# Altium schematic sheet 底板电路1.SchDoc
size 1099 x 400 mm; SheetNumber: 2; SheetTotal: 2
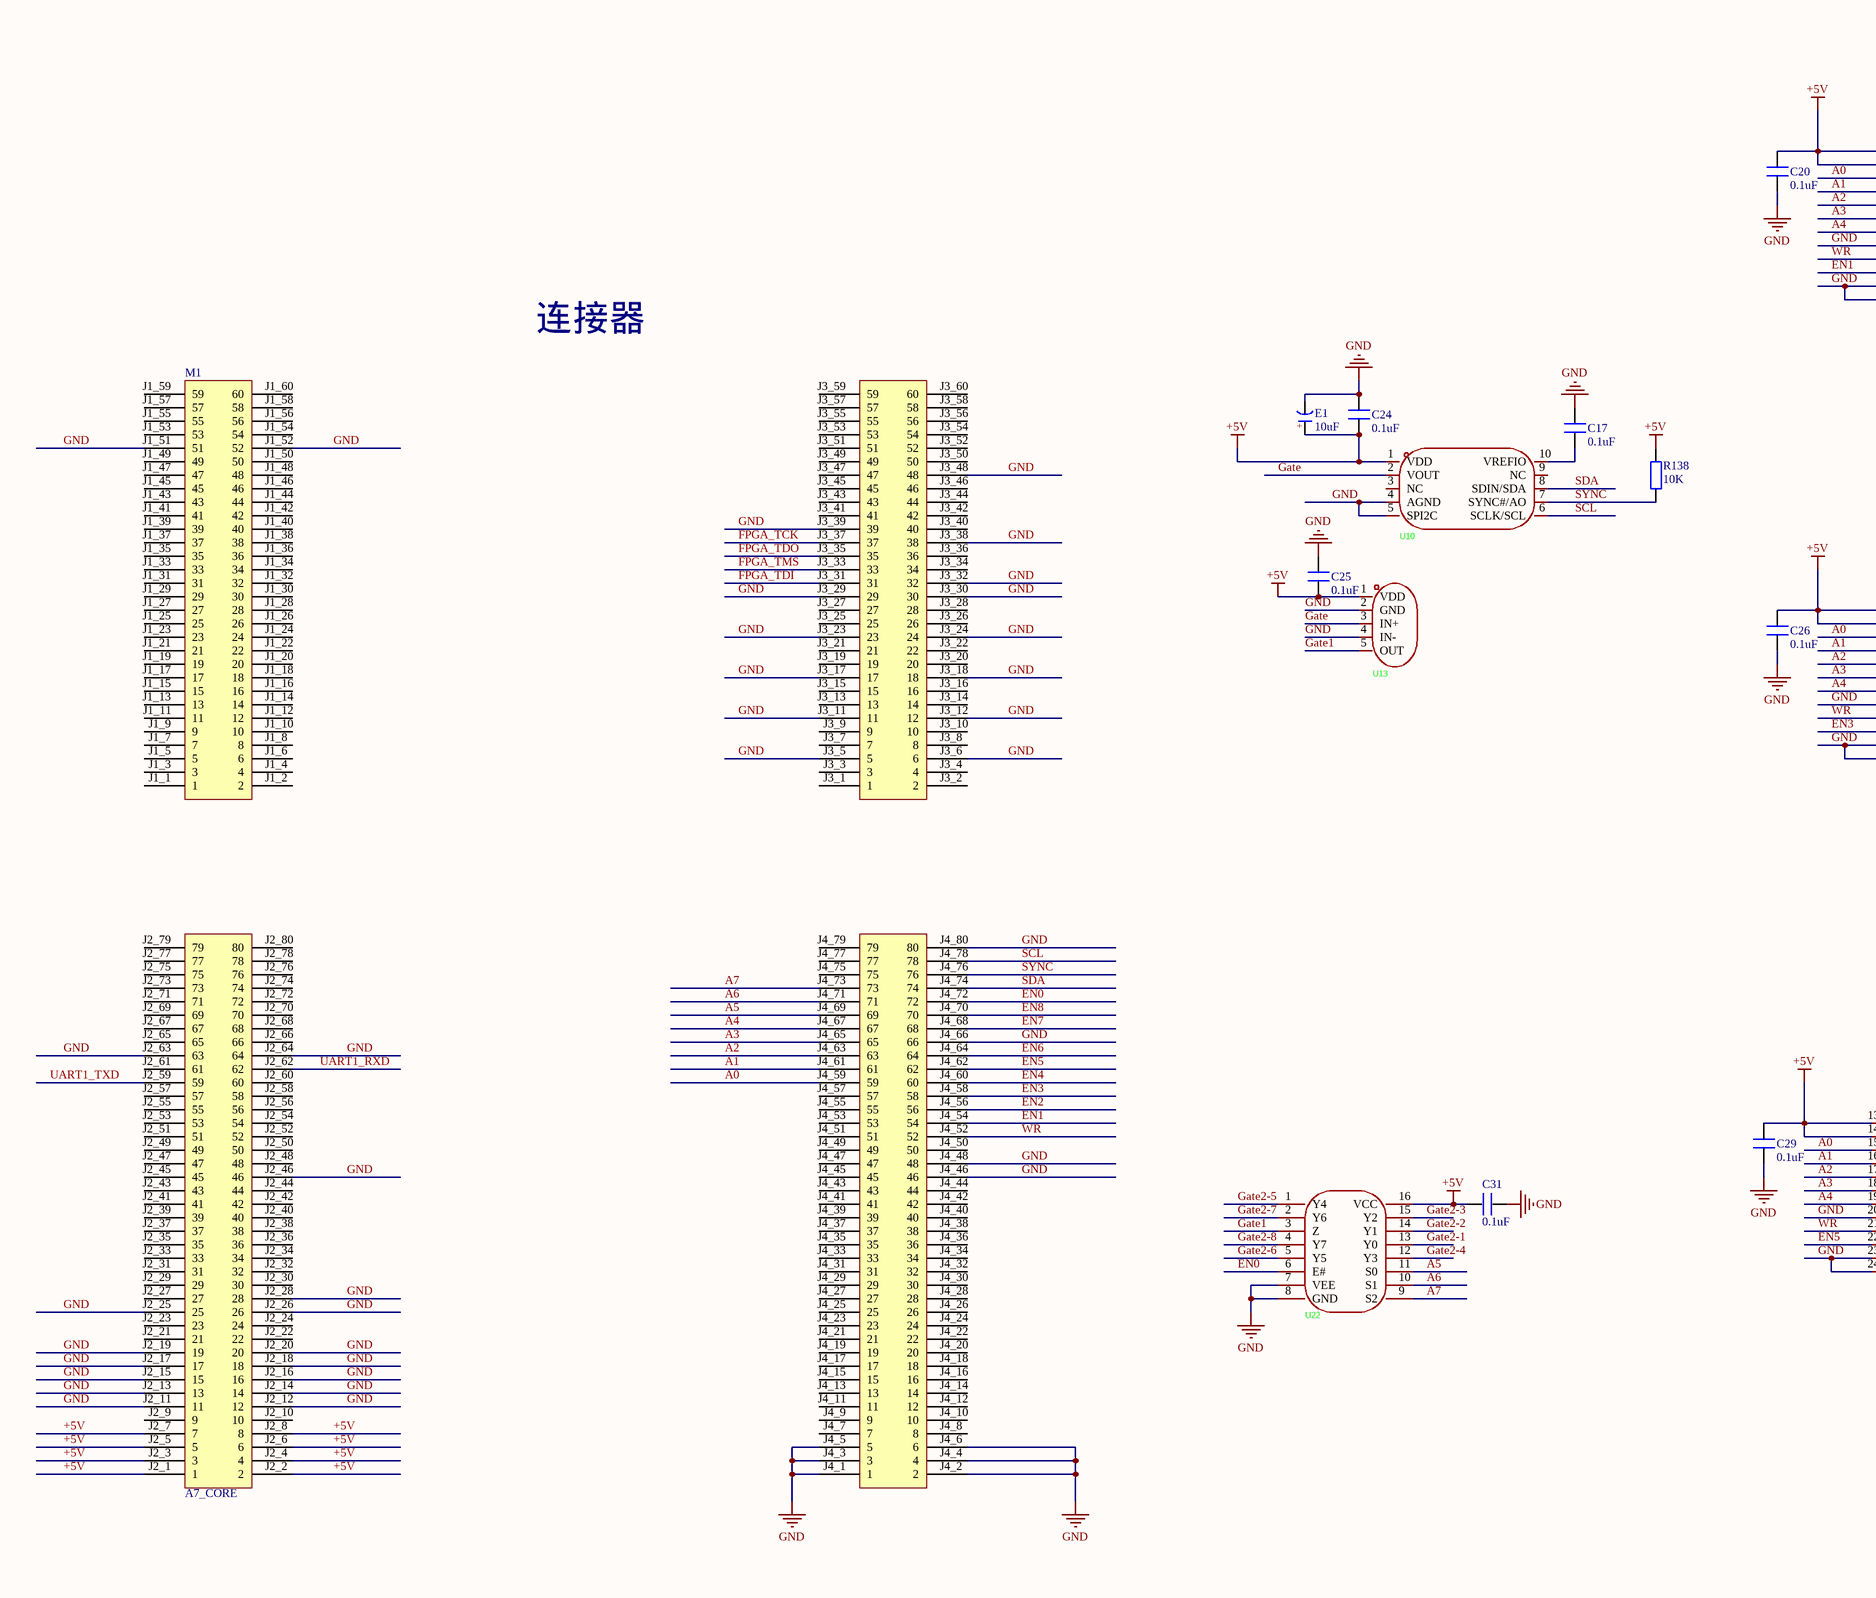
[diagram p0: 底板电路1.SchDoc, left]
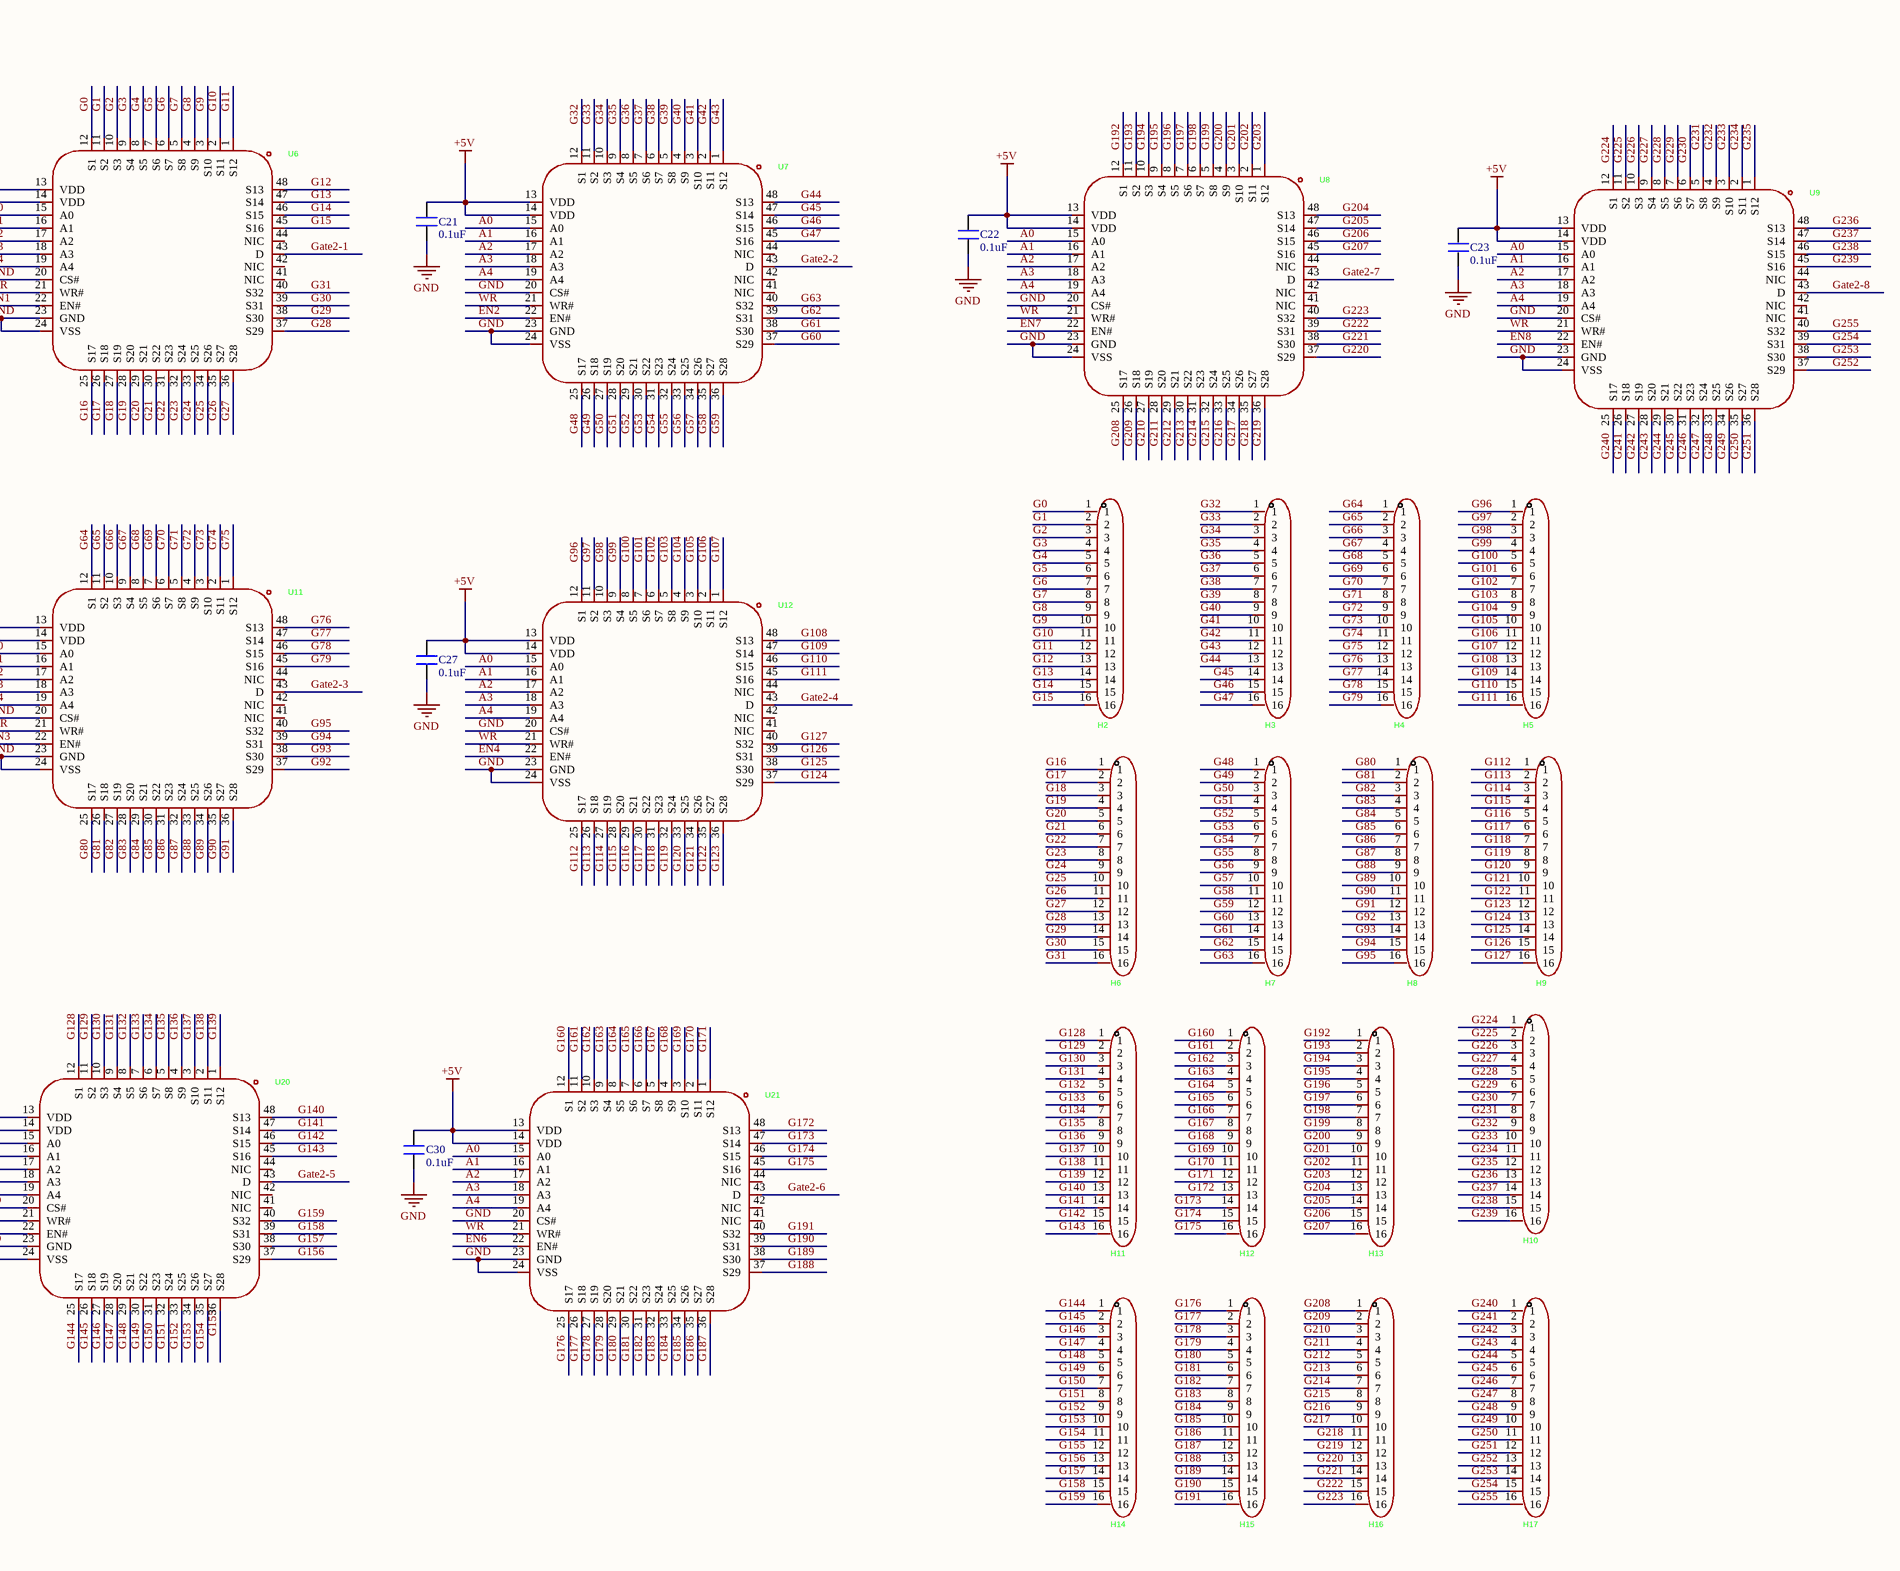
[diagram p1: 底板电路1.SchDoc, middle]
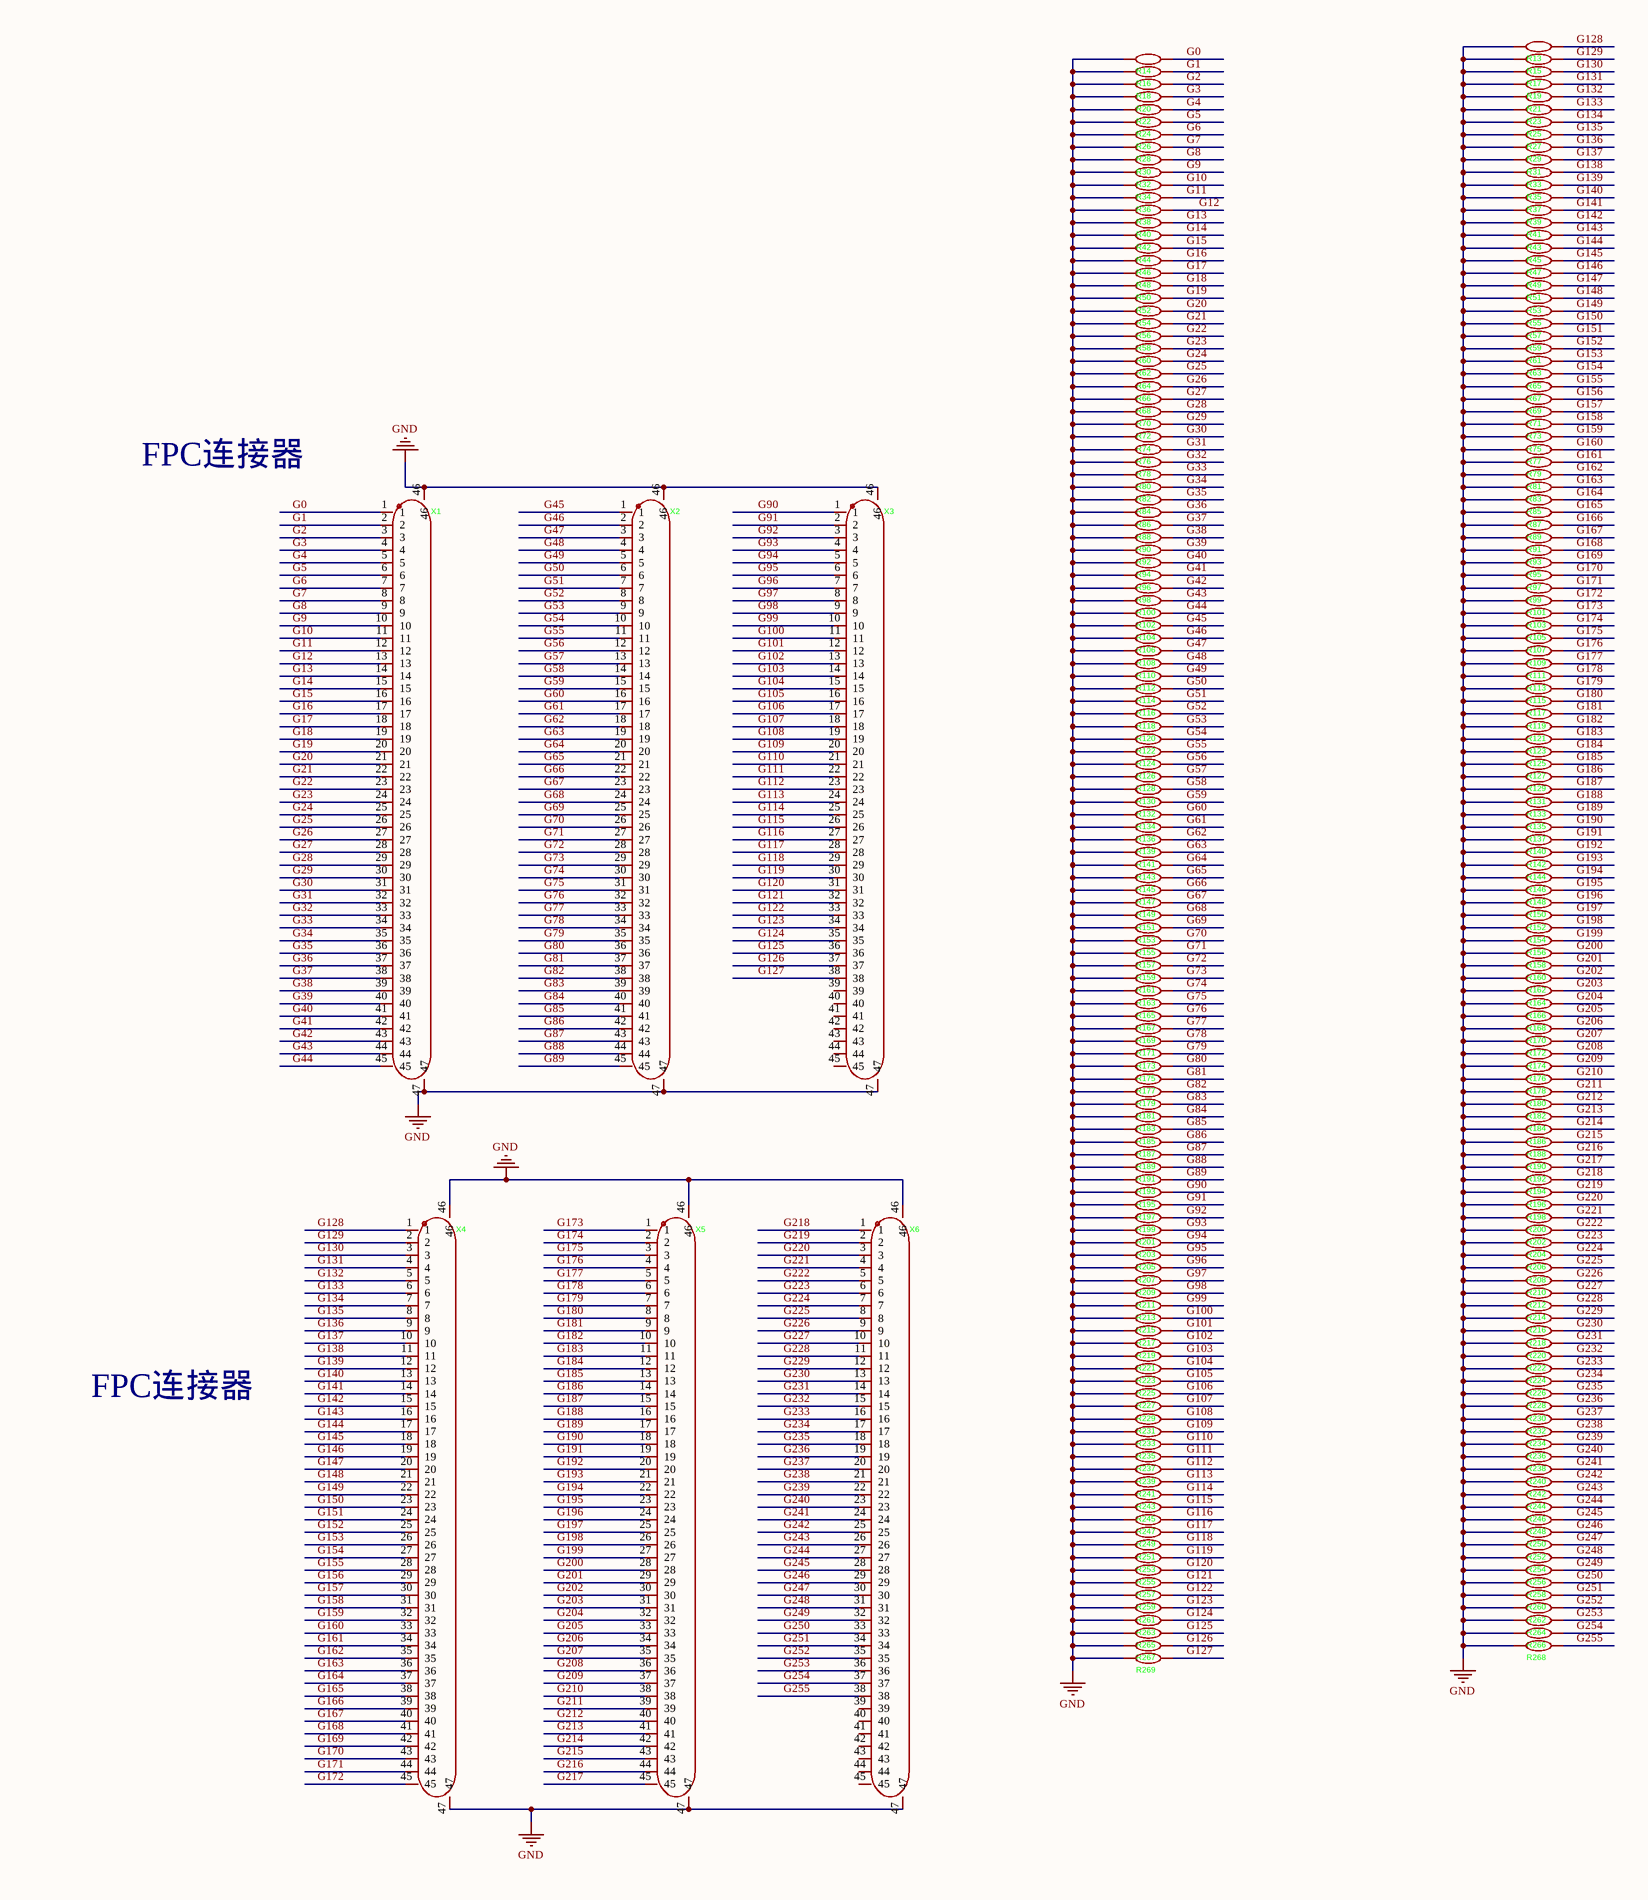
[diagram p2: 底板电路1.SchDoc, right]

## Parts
C17  0.1uF  [0603P]
C20  0.1uF  [0603P]
C21  0.1uF  [0603P]
C22  0.1uF  [0603P]
C23  0.1uF  [0603P]
C24  0.1uF  [0603P]
C25  0.1uF  [0603P]
C26  0.1uF  [0603P]
C27  0.1uF  [0603P]
C29  0.1uF  [0603P]
C30  0.1uF  [0603P]
C31  0.1uF  [0603P]
E1  10uF  [CD S(2012)]
H2  BX-PZ1.27-1-16PZZ  [HDR-TH_16P-P1.27-V-M]  (value not drawn)
H3  BX-PZ1.27-1-16PZZ  [HDR-TH_16P-P1.27-V-M]  (value not drawn)
H4  BX-PZ1.27-1-16PZZ  [HDR-TH_16P-P1.27-V-M]  (value not drawn)
H5  BX-PZ1.27-1-16PZZ  [HDR-TH_16P-P1.27-V-M]  (value not drawn)
H6  BX-PZ1.27-1-16PZZ  [HDR-TH_16P-P1.27-V-M]  (value not drawn)
H7  BX-PZ1.27-1-16PZZ  [HDR-TH_16P-P1.27-V-M]  (value not drawn)
H8  BX-PZ1.27-1-16PZZ  [HDR-TH_16P-P1.27-V-M]  (value not drawn)
H9  BX-PZ1.27-1-16PZZ  [HDR-TH_16P-P1.27-V-M]  (value not drawn)
H10  BX-PZ1.27-1-16PZZ  [HDR-TH_16P-P1.27-V-M]  (value not drawn)
H11  BX-PZ1.27-1-16PZZ  [HDR-TH_16P-P1.27-V-M]  (value not drawn)
H12  BX-PZ1.27-1-16PZZ  [HDR-TH_16P-P1.27-V-M]  (value not drawn)
H13  BX-PZ1.27-1-16PZZ  [HDR-TH_16P-P1.27-V-M]  (value not drawn)
H14  BX-PZ1.27-1-16PZZ  [HDR-TH_16P-P1.27-V-M]  (value not drawn)
H15  BX-PZ1.27-1-16PZZ  [HDR-TH_16P-P1.27-V-M]  (value not drawn)
H16  BX-PZ1.27-1-16PZZ  [HDR-TH_16P-P1.27-V-M]  (value not drawn)
H17  BX-PZ1.27-1-16PZZ  [HDR-TH_16P-P1.27-V-M]  (value not drawn)
M1  A7_CORE  [ARTIX7_Core]
R13  10kΩ  [R0402]  (value not drawn)
R14  10kΩ  [R0402]  (value not drawn)
R15  10kΩ  [R0402]  (value not drawn)
R16  10kΩ  [R0402]  (value not drawn)
R17  10kΩ  [R0402]  (value not drawn)
R18  10kΩ  [R0402]  (value not drawn)
R19  10kΩ  [R0402]  (value not drawn)
R20  10kΩ  [R0402]  (value not drawn)
R21  10kΩ  [R0402]  (value not drawn)
R22  10kΩ  [R0402]  (value not drawn)
R23  10kΩ  [R0402]  (value not drawn)
R24  10kΩ  [R0402]  (value not drawn)
R25  10kΩ  [R0402]  (value not drawn)
R26  10kΩ  [R0402]  (value not drawn)
R27  10kΩ  [R0402]  (value not drawn)
R28  10kΩ  [R0402]  (value not drawn)
R29  10kΩ  [R0402]  (value not drawn)
R30  10kΩ  [R0402]  (value not drawn)
R31  10kΩ  [R0402]  (value not drawn)
R32  10kΩ  [R0402]  (value not drawn)
R33  10kΩ  [R0402]  (value not drawn)
R34  10kΩ  [R0402]  (value not drawn)
R35  10kΩ  [R0402]  (value not drawn)
R36  10kΩ  [R0402]  (value not drawn)
R37  10kΩ  [R0402]  (value not drawn)
R38  10kΩ  [R0402]  (value not drawn)
R39  10kΩ  [R0402]  (value not drawn)
R40  10kΩ  [R0402]  (value not drawn)
R41  10kΩ  [R0402]  (value not drawn)
R42  10kΩ  [R0402]  (value not drawn)
R43  10kΩ  [R0402]  (value not drawn)
R44  10kΩ  [R0402]  (value not drawn)
R45  10kΩ  [R0402]  (value not drawn)
R46  10kΩ  [R0402]  (value not drawn)
R47  10kΩ  [R0402]  (value not drawn)
R48  10kΩ  [R0402]  (value not drawn)
R49  10kΩ  [R0402]  (value not drawn)
R50  10kΩ  [R0402]  (value not drawn)
R51  10kΩ  [R0402]  (value not drawn)
R52  10kΩ  [R0402]  (value not drawn)
R53  10kΩ  [R0402]  (value not drawn)
R54  10kΩ  [R0402]  (value not drawn)
R55  10kΩ  [R0402]  (value not drawn)
R56  10kΩ  [R0402]  (value not drawn)
R57  10kΩ  [R0402]  (value not drawn)
R58  10kΩ  [R0402]  (value not drawn)
R59  10kΩ  [R0402]  (value not drawn)
R60  10kΩ  [R0402]  (value not drawn)
R61  10kΩ  [R0402]  (value not drawn)
R62  10kΩ  [R0402]  (value not drawn)
R63  10kΩ  [R0402]  (value not drawn)
R64  10kΩ  [R0402]  (value not drawn)
R65  10kΩ  [R0402]  (value not drawn)
R66  10kΩ  [R0402]  (value not drawn)
R67  10kΩ  [R0402]  (value not drawn)
R68  10kΩ  [R0402]  (value not drawn)
R69  10kΩ  [R0402]  (value not drawn)
R70  10kΩ  [R0402]  (value not drawn)
R71  10kΩ  [R0402]  (value not drawn)
R72  10kΩ  [R0402]  (value not drawn)
R73  10kΩ  [R0402]  (value not drawn)
R74  10kΩ  [R0402]  (value not drawn)
R75  10kΩ  [R0402]  (value not drawn)
R76  10kΩ  [R0402]  (value not drawn)
R77  10kΩ  [R0402]  (value not drawn)
R78  10kΩ  [R0402]  (value not drawn)
R79  10kΩ  [R0402]  (value not drawn)
R80  10kΩ  [R0402]  (value not drawn)
R81  10kΩ  [R0402]  (value not drawn)
R82  10kΩ  [R0402]  (value not drawn)
R83  10kΩ  [R0402]  (value not drawn)
R84  10kΩ  [R0402]  (value not drawn)
R85  10kΩ  [R0402]  (value not drawn)
R86  10kΩ  [R0402]  (value not drawn)
R87  10kΩ  [R0402]  (value not drawn)
R88  10kΩ  [R0402]  (value not drawn)
R89  10kΩ  [R0402]  (value not drawn)
R90  10kΩ  [R0402]  (value not drawn)
R91  10kΩ  [R0402]  (value not drawn)
R92  10kΩ  [R0402]  (value not drawn)
R93  10kΩ  [R0402]  (value not drawn)
R94  10kΩ  [R0402]  (value not drawn)
R95  10kΩ  [R0402]  (value not drawn)
R96  10kΩ  [R0402]  (value not drawn)
R97  10kΩ  [R0402]  (value not drawn)
R98  10kΩ  [R0402]  (value not drawn)
R99  10kΩ  [R0402]  (value not drawn)
R100  10kΩ  [R0402]  (value not drawn)
R101  10kΩ  [R0402]  (value not drawn)
R102  10kΩ  [R0402]  (value not drawn)
R103  10kΩ  [R0402]  (value not drawn)
R104  10kΩ  [R0402]  (value not drawn)
R105  10kΩ  [R0402]  (value not drawn)
R106  10kΩ  [R0402]  (value not drawn)
R107  10kΩ  [R0402]  (value not drawn)
R108  10kΩ  [R0402]  (value not drawn)
R109  10kΩ  [R0402]  (value not drawn)
R110  10kΩ  [R0402]  (value not drawn)
R111  10kΩ  [R0402]  (value not drawn)
R112  10kΩ  [R0402]  (value not drawn)
R113  10kΩ  [R0402]  (value not drawn)
R114  10kΩ  [R0402]  (value not drawn)
R115  10kΩ  [R0402]  (value not drawn)
R116  10kΩ  [R0402]  (value not drawn)
R117  10kΩ  [R0402]  (value not drawn)
R118  10kΩ  [R0402]  (value not drawn)
R119  10kΩ  [R0402]  (value not drawn)
R120  10kΩ  [R0402]  (value not drawn)
R121  10kΩ  [R0402]  (value not drawn)
R122  10kΩ  [R0402]  (value not drawn)
R123  10kΩ  [R0402]  (value not drawn)
R124  10kΩ  [R0402]  (value not drawn)
R125  10kΩ  [R0402]  (value not drawn)
R126  10kΩ  [R0402]  (value not drawn)
R127  10kΩ  [R0402]  (value not drawn)
R128  10kΩ  [R0402]  (value not drawn)
R129  10kΩ  [R0402]  (value not drawn)
R130  10kΩ  [R0402]  (value not drawn)
R131  10kΩ  [R0402]  (value not drawn)
R132  10kΩ  [R0402]  (value not drawn)
R133  10kΩ  [R0402]  (value not drawn)
R134  10kΩ  [R0402]  (value not drawn)
R135  10kΩ  [R0402]  (value not drawn)
R136  10kΩ  [R0402]  (value not drawn)
R137  10kΩ  [R0402]  (value not drawn)
R138  10K  [R 0603_M]
R139  10kΩ  [R0402]  (value not drawn)
R140  10kΩ  [R0402]  (value not drawn)
R141  10kΩ  [R0402]  (value not drawn)
R142  10kΩ  [R0402]  (value not drawn)
R143  10kΩ  [R0402]  (value not drawn)
R144  10kΩ  [R0402]  (value not drawn)
R145  10kΩ  [R0402]  (value not drawn)
R146  10kΩ  [R0402]  (value not drawn)
R147  10kΩ  [R0402]  (value not drawn)
R148  10kΩ  [R0402]  (value not drawn)
R149  10kΩ  [R0402]  (value not drawn)
R150  10kΩ  [R0402]  (value not drawn)
R151  10kΩ  [R0402]  (value not drawn)
R152  10kΩ  [R0402]  (value not drawn)
R153  10kΩ  [R0402]  (value not drawn)
R154  10kΩ  [R0402]  (value not drawn)
R155  10kΩ  [R0402]  (value not drawn)
R156  10kΩ  [R0402]  (value not drawn)
R157  10kΩ  [R0402]  (value not drawn)
R158  10kΩ  [R0402]  (value not drawn)
R159  10kΩ  [R0402]  (value not drawn)
R160  10kΩ  [R0402]  (value not drawn)
R161  10kΩ  [R0402]  (value not drawn)
R162  10kΩ  [R0402]  (value not drawn)
R163  10kΩ  [R0402]  (value not drawn)
R164  10kΩ  [R0402]  (value not drawn)
R165  10kΩ  [R0402]  (value not drawn)
R166  10kΩ  [R0402]  (value not drawn)
R167  10kΩ  [R0402]  (value not drawn)
R168  10kΩ  [R0402]  (value not drawn)
R169  10kΩ  [R0402]  (value not drawn)
R170  10kΩ  [R0402]  (value not drawn)
R171  10kΩ  [R0402]  (value not drawn)
R172  10kΩ  [R0402]  (value not drawn)
R173  10kΩ  [R0402]  (value not drawn)
R174  10kΩ  [R0402]  (value not drawn)
R175  10kΩ  [R0402]  (value not drawn)
R176  10kΩ  [R0402]  (value not drawn)
R177  10kΩ  [R0402]  (value not drawn)
R178  10kΩ  [R0402]  (value not drawn)
R179  10kΩ  [R0402]  (value not drawn)
R180  10kΩ  [R0402]  (value not drawn)
R181  10kΩ  [R0402]  (value not drawn)
R182  10kΩ  [R0402]  (value not drawn)
R183  10kΩ  [R0402]  (value not drawn)
R184  10kΩ  [R0402]  (value not drawn)
R185  10kΩ  [R0402]  (value not drawn)
R186  10kΩ  [R0402]  (value not drawn)
R187  10kΩ  [R0402]  (value not drawn)
R188  10kΩ  [R0402]  (value not drawn)
R189  10kΩ  [R0402]  (value not drawn)
R190  10kΩ  [R0402]  (value not drawn)
R191  10kΩ  [R0402]  (value not drawn)
R192  10kΩ  [R0402]  (value not drawn)
R193  10kΩ  [R0402]  (value not drawn)
R194  10kΩ  [R0402]  (value not drawn)
R195  10kΩ  [R0402]  (value not drawn)
R196  10kΩ  [R0402]  (value not drawn)
R197  10kΩ  [R0402]  (value not drawn)
R198  10kΩ  [R0402]  (value not drawn)
R199  10kΩ  [R0402]  (value not drawn)
R200  10kΩ  [R0402]  (value not drawn)
R201  10kΩ  [R0402]  (value not drawn)
R202  10kΩ  [R0402]  (value not drawn)
R203  10kΩ  [R0402]  (value not drawn)
R204  10kΩ  [R0402]  (value not drawn)
R205  10kΩ  [R0402]  (value not drawn)
R206  10kΩ  [R0402]  (value not drawn)
R207  10kΩ  [R0402]  (value not drawn)
R208  10kΩ  [R0402]  (value not drawn)
R209  10kΩ  [R0402]  (value not drawn)
R210  10kΩ  [R0402]  (value not drawn)
R211  10kΩ  [R0402]  (value not drawn)
R212  10kΩ  [R0402]  (value not drawn)
R213  10kΩ  [R0402]  (value not drawn)
R214  10kΩ  [R0402]  (value not drawn)
R215  10kΩ  [R0402]  (value not drawn)
R216  10kΩ  [R0402]  (value not drawn)
R217  10kΩ  [R0402]  (value not drawn)
R218  10kΩ  [R0402]  (value not drawn)
R219  10kΩ  [R0402]  (value not drawn)
R220  10kΩ  [R0402]  (value not drawn)
R221  10kΩ  [R0402]  (value not drawn)
R222  10kΩ  [R0402]  (value not drawn)
R223  10kΩ  [R0402]  (value not drawn)
R224  10kΩ  [R0402]  (value not drawn)
R225  10kΩ  [R0402]  (value not drawn)
R226  10kΩ  [R0402]  (value not drawn)
R227  10kΩ  [R0402]  (value not drawn)
R228  10kΩ  [R0402]  (value not drawn)
R229  10kΩ  [R0402]  (value not drawn)
R230  10kΩ  [R0402]  (value not drawn)
R231  10kΩ  [R0402]  (value not drawn)
R232  10kΩ  [R0402]  (value not drawn)
R233  10kΩ  [R0402]  (value not drawn)
R234  10kΩ  [R0402]  (value not drawn)
R235  10kΩ  [R0402]  (value not drawn)
R236  10kΩ  [R0402]  (value not drawn)
R237  10kΩ  [R0402]  (value not drawn)
R238  10kΩ  [R0402]  (value not drawn)
R239  10kΩ  [R0402]  (value not drawn)
R240  10kΩ  [R0402]  (value not drawn)
R241  10kΩ  [R0402]  (value not drawn)
R242  10kΩ  [R0402]  (value not drawn)
R243  10kΩ  [R0402]  (value not drawn)
R244  10kΩ  [R0402]  (value not drawn)
R245  10kΩ  [R0402]  (value not drawn)
R246  10kΩ  [R0402]  (value not drawn)
R247  10kΩ  [R0402]  (value not drawn)
R248  10kΩ  [R0402]  (value not drawn)
R249  10kΩ  [R0402]  (value not drawn)
R250  10kΩ  [R0402]  (value not drawn)
R251  10kΩ  [R0402]  (value not drawn)
R252  10kΩ  [R0402]  (value not drawn)
R253  10kΩ  [R0402]  (value not drawn)
R254  10kΩ  [R0402]  (value not drawn)
R255  10kΩ  [R0402]  (value not drawn)
R256  10kΩ  [R0402]  (value not drawn)
R257  10kΩ  [R0402]  (value not drawn)
R258  10kΩ  [R0402]  (value not drawn)
R259  10kΩ  [R0402]  (value not drawn)
R260  10kΩ  [R0402]  (value not drawn)
R261  10kΩ  [R0402]  (value not drawn)
R262  10kΩ  [R0402]  (value not drawn)
R263  10kΩ  [R0402]  (value not drawn)
R264  10kΩ  [R0402]  (value not drawn)
R265  10kΩ  [R0402]  (value not drawn)
R266  10kΩ  [R0402]  (value not drawn)
R267  10kΩ  [R0402]  (value not drawn)
R268  10kΩ  [R0402]  (value not drawn)
R269  10kΩ  [R0402]  (value not drawn)
U6  ADG732BSUZ-REEL  [TQFP-48_L7.0-W7.0-P0.50-LS9.0-TL]  (value not drawn)
U7  ADG732BSUZ-REEL  [TQFP-48_L7.0-W7.0-P0.50-LS9.0-TL]  (value not drawn)
U8  ADG732BSUZ-REEL  [TQFP-48_L7.0-W7.0-P0.50-LS9.0-TL]  (value not drawn)
U9  ADG732BSUZ-REEL  [TQFP-48_L7.0-W7.0-P0.50-LS9.0-TL]  (value not drawn)
U10  DAC80501ZDGSR  [VSSOP-10_L3.0-W3.0-P0.50-LS4.9-BL]  (value not drawn)
U11  ADG732BSUZ-REEL  [TQFP-48_L7.0-W7.0-P0.50-LS9.0-TL]  (value not drawn)
U12  ADG732BSUZ-REEL  [TQFP-48_L7.0-W7.0-P0.50-LS9.0-TL]  (value not drawn)
U13  UCC27517DBVR  [SOT-23-5_L3.0-W1.7-P0.95-LS2.8-BR]  (value not drawn)
U20  ADG732BSUZ-REEL  [TQFP-48_L7.0-W7.0-P0.50-LS9.0-TL]  (value not drawn)
U21  ADG732BSUZ-REEL  [TQFP-48_L7.0-W7.0-P0.50-LS9.0-TL]  (value not drawn)
U22  74HC4051PW,118  [TSSOP-16_L5.0-W4.4-P0.65-LS6.4-BL]  (value not drawn)
X1  AFC01-S45FCA-00  [FPC-SMD_AFC01-S45FCA-00]  (value not drawn)
X2  AFC01-S45FCA-00  [FPC-SMD_AFC01-S45FCA-00]  (value not drawn)
X3  AFC01-S45FCA-00  [FPC-SMD_AFC01-S45FCA-00]  (value not drawn)
X4  AFC01-S45FCA-00  [FPC-SMD_AFC01-S45FCA-00]  (value not drawn)
X5  AFC01-S45FCA-00  [FPC-SMD_AFC01-S45FCA-00]  (value not drawn)
X6  AFC01-S45FCA-00  [FPC-SMD_AFC01-S45FCA-00]  (value not drawn)

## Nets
+5V: C20.1 C21.1 C22.1 C23.1 C24.2 C25.2 C26.1 C27.1 C29.1 C30.1 C31.1 E1.1(A) M1.J2_1(1) M1.J2_2(2) M1.J2_3(3) M1.J2_4(4) M1.J2_5(5) M1.J2_6(6) M1.J2_7(7) M1.J2_8(8) R138.2 U6.13(VDD) U6.14(VDD) U7.13(VDD) U7.14(VDD) U8.13(VDD) U8.14(VDD) U9.13(VDD) U9.14(VDD) U10.1(VDD) U11.13(VDD) U11.14(VDD) U12.13(VDD) U12.14(VDD) U13.1(VDD) U20.13(VDD) U20.14(VDD) U21.13(VDD) U21.14(VDD) U22.16(VCC)
GND: C17.1 C20.2 C21.2 C22.2 C23.2 C24.1 C25.1 C26.2 C27.2 C29.2 C30.2 C31.2 E1.2(K) M1.J1_51(51) M1.J1_52(52) M1.J2_11(11) M1.J2_12(12) M1.J2_13(13) M1.J2_14(14) M1.J2_15(15) M1.J2_16(16) M1.J2_17(17) M1.J2_18(18) M1.J2_19(19) M1.J2_20(20) M1.J2_25(25) M1.J2_26(26) M1.J2_28(28) M1.J2_46(46) M1.J2_63(63) M1.J2_64(64) M1.J3_5(5) M1.J3_6(6) M1.J3_11(11) M1.J3_12(12) M1.J3_17(17) M1.J3_18(18) M1.J3_23(23) M1.J3_24(24) M1.J3_29(29) M1.J3_30(30) M1.J3_32(32) M1.J3_38(38) M1.J3_39(39) M1.J3_48(48) M1.J4_1(1) M1.J4_2(2) M1.J4_3(3) M1.J4_4(4) M1.J4_5(5) M1.J4_6(6) M1.J4_46(46) M1.J4_48(48) M1.J4_66(66) M1.J4_80(80) R13.1 R14.1 R15.1 R16.1 R17.1 R18.1 R19.1 R20.1 R21.1 R22.1 R23.1 R24.1 R25.1 R26.1 R27.1 R28.1 R29.1 R30.1 R31.1 R32.1 R33.1 R34.1 R35.1 R36.1 R37.1 R38.1 R39.1 R40.1 R41.1 R42.1 R43.1 R44.1 R45.1 R46.1 R47.1 R48.1 R49.1 R50.1 R51.1 R52.1 R53.1 R54.1 R55.1 R56.1 R57.1 R58.1 R59.1 R60.1 R61.1 R62.1 R63.1 R64.1 R65.1 R66.1 R67.1 R68.1 R69.1 R70.1 R71.1 R72.1 R73.1 R74.1 R75.1 R76.1 R77.1 R78.1 R79.1 R80.1 R81.1 R82.1 R83.1 R84.1 R85.1 R86.1 R87.1 R88.1 R89.1 R90.1 R91.1 R92.1 R93.1 R94.1 R95.1 R96.1 R97.1 R98.1 R99.1 R100.1 R101.1 R102.1 R103.1 R104.1 R105.1 R106.1 R107.1 R108.1 R109.1 R110.1 R111.1 R112.1 R113.1 R114.1 R115.1 R116.1 R117.1 R118.1 R119.1 R120.1 R121.1 R122.1 R123.1 R124.1 R125.1 R126.1 R127.1 R128.1 R129.1 R130.1 R131.1 R132.1 R133.1 R134.1 R135.1 R136.1 R137.1 R139.1 R140.1 R141.1 R142.1 R143.1 R144.1 R145.1 R146.1 R147.1 R148.1 R149.1 R150.1 R151.1 R152.1 R153.1 R154.1 R155.1 R156.1 R157.1 R158.1 R159.1 R160.1 R161.1 R162.1 R163.1 R164.1 R165.1 R166.1 R167.1 R168.1 R169.1 R170.1 R171.1 R172.1 R173.1 R174.1 R175.1 R176.1 R177.1 R178.1 R179.1 R180.1 R181.1 R182.1 R183.1 R184.1 R185.1 R186.1 R187.1 R188.1 R189.1 R190.1 R191.1 R192.1 R193.1 R194.1 R195.1 R196.1 R197.1 R198.1 R199.1 R200.1 R201.1 R202.1 R203.1 R204.1 R205.1 R206.1 R207.1 R208.1 R209.1 R210.1 R211.1 R212.1 R213.1 R214.1 R215.1 R216.1 R217.1 R218.1 R219.1 R220.1 R221.1 R222.1 R223.1 R224.1 R225.1 R226.1 R227.1 R228.1 R229.1 R230.1 R231.1 R232.1 R233.1 R234.1 R235.1 R236.1 R237.1 R238.1 R239.1 R240.1 R241.1 R242.1 R243.1 R244.1 R245.1 R246.1 R247.1 R248.1 R249.1 R250.1 R251.1 R252.1 R253.1 R254.1 R255.1 R256.1 R257.1 R258.1 R259.1 R260.1 R261.1 R262.1 R263.1 R264.1 R265.1 R266.1 R267.1 R268.1 R269.1 U6.20(CS#) U6.23(GND) U6.24(VSS) U7.20(CS#) U7.23(GND) U7.24(VSS) U8.20(CS#) U8.23(GND) U8.24(VSS) U9.20(CS#) U9.23(GND) U9.24(VSS) U10.4(AGND) U10.5(SPI2C) U11.20(CS#) U11.23(GND) U11.24(VSS) U12.20(CS#) U12.23(GND) U12.24(VSS) U13.2(GND) U13.4(IN-) U20.20(CS#) U20.23(GND) U20.24(VSS) U21.20(CS#) U21.23(GND) U21.24(VSS) U22.7(VEE) U22.8(GND) X1.46 X1.47 X2.46 X2.47 X3.46 X3.47 X4.46 X4.47 X5.46 X5.47 X6.46 X6.47
A0: M1.J4_59(59) U6.15(A0) U7.15(A0) U8.15(A0) U9.15(A0) U11.15(A0) U12.15(A0) U20.15(A0) U21.15(A0)
A1: M1.J4_61(61) U6.16(A1) U7.16(A1) U8.16(A1) U9.16(A1) U11.16(A1) U12.16(A1) U20.16(A1) U21.16(A1)
A2: M1.J4_63(63) U6.17(A2) U7.17(A2) U8.17(A2) U9.17(A2) U11.17(A2) U12.17(A2) U20.17(A2) U21.17(A2)
A3: M1.J4_65(65) U6.18(A3) U7.18(A3) U8.18(A3) U9.18(A3) U11.18(A3) U12.18(A3) U20.18(A3) U21.18(A3)
A4: M1.J4_67(67) U6.19(A4) U7.19(A4) U8.19(A4) U9.19(A4) U11.19(A4) U12.19(A4) U20.19(A4) U21.19(A4)
A5: M1.J4_69(69) U22.11(S0)
A6: M1.J4_71(71) U22.10(S1)
A7: M1.J4_73(73) U22.9(S2)
EN0: M1.J4_72(72) U22.6(E#)
EN1: M1.J4_54(54) U6.22(EN#)
EN2: M1.J4_56(56) U7.22(EN#)
EN3: M1.J4_58(58) U11.22(EN#)
EN4: M1.J4_60(60) U12.22(EN#)
EN5: M1.J4_62(62) U20.22(EN#)
EN6: M1.J4_64(64) U21.22(EN#)
EN7: M1.J4_68(68) U8.22(EN#)
EN8: M1.J4_70(70) U9.22(EN#)
FPGA_TCK: M1.J3_37(37)
FPGA_TDI: M1.J3_31(31)
FPGA_TDO: M1.J3_35(35)
FPGA_TMS: M1.J3_33(33)
G0: H2.1 R14.2 U6.12(S1) X1.1
G1: H2.2 R16.2 U6.11(S2) X1.2
G2: H2.3 R18.2 U6.10(S3) X1.3
G3: H2.4 R20.2 U6.9(S4) X1.4
G4: H2.5 R22.2 U6.8(S5) X1.5
G5: H2.6 R24.2 U6.7(S6) X1.6
G6: H2.7 R26.2 U6.6(S7) X1.7
G7: H2.8 R28.2 U6.5(S8) X1.8
G8: H2.9 R30.2 U6.4(S9) X1.9
G9: H2.10 R32.2 U6.3(S10) X1.10
G10: H2.11 R34.2 U6.2(S11) X1.11
G11: H2.12 R36.2 U6.1(S12) X1.12
G12: H2.13 R38.2 U6.48(S13) X1.13
G13: H2.14 R40.2 U6.47(S14) X1.14
G14: H2.15 R42.2 U6.46(S15) X1.15
G15: H2.16 R44.2 U6.45(S16) X1.16
G16: H6.1 R46.2 U6.25(S17) X1.17
G17: H6.2 R48.2 U6.26(S18) X1.18
G18: H6.3 R50.2 U6.27(S19) X1.19
G19: H6.4 R52.2 U6.28(S20) X1.20
G20: H6.5 R54.2 U6.29(S21) X1.21
G21: H6.6 R56.2 U6.30(S22) X1.22
G22: H6.7 R58.2 U6.31(S23) X1.23
G23: H6.8 R60.2 U6.32(S24) X1.24
G24: H6.9 R62.2 U6.33(S25) X1.25
G25: H6.10 R64.2 U6.34(S26) X1.26
G26: H6.11 R66.2 U6.35(S27) X1.27
G27: H6.12 R68.2 U6.36(S28) X1.28
G28: H6.13 R70.2 U6.37(S29) X1.29
G29: H6.14 R72.2 U6.38(S30) X1.30
G30: H6.15 R74.2 U6.39(S31) X1.31
G31: H6.16 R76.2 U6.40(S32) X1.32
G32: H3.1 R78.2 U7.12(S1) X1.33
G33: H3.2 R80.2 U7.11(S2) X1.34
G34: H3.3 R82.2 U7.10(S3) X1.35
G35: H3.4 R84.2 U7.9(S4) X1.36
G36: H3.5 R86.2 U7.8(S5) X1.37
G37: H3.6 R88.2 U7.7(S6) X1.38
G38: H3.7 R90.2 U7.6(S7) X1.39
G39: H3.8 R92.2 U7.5(S8) X1.40
G40: H3.9 R94.2 U7.4(S9) X1.41
G41: H3.10 R96.2 U7.3(S10) X1.42
G42: H3.11 R98.2 U7.2(S11) X1.43
G43: H3.12 R100.2 U7.1(S12) X1.44
G44: H3.13 R102.2 U7.48(S13) X1.45
G45: H3.14 R104.2 U7.47(S14) X2.1
G46: H3.15 R106.2 U7.46(S15) X2.2
G47: H3.16 R108.2 U7.45(S16) X2.3
G48: H7.1 R110.2 U7.25(S17) X2.4
G49: H7.2 R112.2 U7.26(S18) X2.5
G50: H7.3 R114.2 U7.27(S19) X2.6
G51: H7.4 R116.2 U7.28(S20) X2.7
G52: H7.5 R118.2 U7.29(S21) X2.8
G53: H7.6 R120.2 U7.30(S22) X2.9
G54: H7.7 R122.2 U7.31(S23) X2.10
G55: H7.8 R124.2 U7.32(S24) X2.11
G56: H7.9 R126.2 U7.33(S25) X2.12
G57: H7.10 R128.2 U7.34(S26) X2.13
G58: H7.11 R130.2 U7.35(S27) X2.14
G59: H7.12 R132.2 U7.36(S28) X2.15
G60: H7.13 R134.2 U7.37(S29) X2.16
G61: H7.14 R136.2 U7.38(S30) X2.17
G62: H7.15 R139.2 U7.39(S31) X2.18
G63: H7.16 R141.2 U7.40(S32) X2.19
G64: H4.1 R143.2 U11.12(S1) X2.20
G65: H4.2 R145.2 U11.11(S2) X2.21
G66: H4.3 R147.2 U11.10(S3) X2.22
G67: H4.4 R149.2 U11.9(S4) X2.23
G68: H4.5 R151.2 U11.8(S5) X2.24
G69: H4.6 R153.2 U11.7(S6) X2.25
G70: H4.7 R155.2 U11.6(S7) X2.26
G71: H4.8 R157.2 U11.5(S8) X2.27
G72: H4.9 R159.2 U11.4(S9) X2.28
G73: H4.10 R161.2 U11.3(S10) X2.29
G74: H4.11 R163.2 U11.2(S11) X2.30
G75: H4.12 R165.2 U11.1(S12) X2.31
G76: H4.13 R167.2 U11.48(S13) X2.32
G77: H4.14 R169.2 U11.47(S14) X2.33
G78: H4.15 R171.2 U11.46(S15) X2.34
G79: H4.16 R173.2 U11.45(S16) X2.35
G80: H8.1 R175.2 U11.25(S17) X2.36
G81: H8.2 R177.2 U11.26(S18) X2.37
G82: H8.3 R179.2 U11.27(S19) X2.38
G83: H8.4 R181.2 U11.28(S20) X2.39
G84: H8.5 R183.2 U11.29(S21) X2.40
G85: H8.6 R185.2 U11.30(S22) X2.41
G86: H8.7 R187.2 U11.31(S23) X2.42
G87: H8.8 R189.2 U11.32(S24) X2.43
G88: H8.9 R191.2 U11.33(S25) X2.44
G89: H8.10 R193.2 U11.34(S26) X2.45
G90: H8.11 R195.2 U11.35(S27) X3.1
G91: H8.12 R197.2 U11.36(S28) X3.2
G92: H8.13 R199.2 U11.37(S29) X3.3
G93: H8.14 R201.2 U11.38(S30) X3.4
G94: H8.15 R203.2 U11.39(S31) X3.5
G95: H8.16 R205.2 U11.40(S32) X3.6
G96: H5.1 R207.2 U12.12(S1) X3.7
G97: H5.2 R209.2 U12.11(S2) X3.8
G98: H5.3 R211.2 U12.10(S3) X3.9
G99: H5.4 R213.2 U12.9(S4) X3.10
G100: H5.5 R215.2 U12.8(S5) X3.11
G101: H5.6 R217.2 U12.7(S6) X3.12
G102: H5.7 R219.2 U12.6(S7) X3.13
G103: H5.8 R221.2 U12.5(S8) X3.14
G104: H5.9 R223.2 U12.4(S9) X3.15
G105: H5.10 R225.2 U12.3(S10) X3.16
G106: H5.11 R227.2 U12.2(S11) X3.17
G107: H5.12 R229.2 U12.1(S12) X3.18
G108: H5.13 R231.2 U12.48(S13) X3.19
G109: H5.14 R233.2 U12.47(S14) X3.20
G110: H5.15 R235.2 U12.46(S15) X3.21
G111: H5.16 R237.2 U12.45(S16) X3.22
G112: H9.1 R239.2 U12.25(S17) X3.23
G113: H9.2 R241.2 U12.26(S18) X3.24
G114: H9.3 R243.2 U12.27(S19) X3.25
G115: H9.4 R245.2 U12.28(S20) X3.26
G116: H9.5 R247.2 U12.29(S21) X3.27
G117: H9.6 R249.2 U12.30(S22) X3.28
G118: H9.7 R251.2 U12.31(S23) X3.29
G119: H9.8 R253.2 U12.32(S24) X3.30
G120: H9.9 R255.2 U12.33(S25) X3.31
G121: H9.10 R257.2 U12.34(S26) X3.32
G122: H9.11 R259.2 U12.35(S27) X3.33
G123: H9.12 R261.2 U12.36(S28) X3.34
G124: H9.13 R263.2 U12.37(S29) X3.35
G125: H9.14 R265.2 U12.38(S30) X3.36
G126: H9.15 R267.2 U12.39(S31) X3.37
G127: H9.16 R269.2 U12.40(S32) X3.38
G128: H11.1 R13.2 U20.12(S1) X4.1
G129: H11.2 R15.2 U20.11(S2) X4.2
G130: H11.3 R17.2 U20.10(S3) X4.3
G131: H11.4 R19.2 U20.9(S4) X4.4
G132: H11.5 R21.2 U20.8(S5) X4.5
G133: H11.6 R23.2 U20.7(S6) X4.6
G134: H11.7 R25.2 U20.6(S7) X4.7
G135: H11.8 R27.2 U20.5(S8) X4.8
G136: H11.9 R29.2 U20.4(S9) X4.9
G137: H11.10 R31.2 U20.3(S10) X4.10
G138: H11.11 R33.2 U20.2(S11) X4.11
G139: H11.12 R35.2 U20.1(S12) X4.12
G140: H11.13 R37.2 U20.48(S13) X4.13
G141: H11.14 R39.2 U20.47(S14) X4.14
G142: H11.15 R41.2 U20.46(S15) X4.15
G143: H11.16 R43.2 U20.45(S16) X4.16
G144: H14.1 R45.2 U20.25(S17) X4.17
G145: H14.2 R47.2 U20.26(S18) X4.18
G146: H14.3 R49.2 U20.27(S19) X4.19
G147: H14.4 R51.2 U20.28(S20) X4.20
G148: H14.5 R53.2 U20.29(S21) X4.21
G149: H14.6 R55.2 U20.30(S22) X4.22
G150: H14.7 R57.2 U20.31(S23) X4.23
G151: H14.8 R59.2 U20.32(S24) X4.24
G152: H14.9 R61.2 U20.33(S25) X4.25
G153: H14.10 R63.2 U20.34(S26) X4.26
G154: H14.11 R65.2 U20.35(S27) X4.27
G155: H14.12 R67.2 U20.36(S28) X4.28
G156: H14.13 R69.2 U20.37(S29) X4.29
G157: H14.14 R71.2 U20.38(S30) X4.30
G158: H14.15 R73.2 U20.39(S31) X4.31
G159: H14.16 R75.2 U20.40(S32) X4.32
G160: H12.1 R77.2 U21.12(S1) X4.33
G161: H12.2 R79.2 U21.11(S2) X4.34
G162: H12.3 R81.2 U21.10(S3) X4.35
G163: H12.4 R83.2 U21.9(S4) X4.36
G164: H12.5 R85.2 U21.8(S5) X4.37
G165: H12.6 R87.2 U21.7(S6) X4.38
G166: H12.7 R89.2 U21.6(S7) X4.39
G167: H12.8 R91.2 U21.5(S8) X4.40
G168: H12.9 R93.2 U21.4(S9) X4.41
G169: H12.10 R95.2 U21.3(S10) X4.42
G170: H12.11 R97.2 U21.2(S11) X4.43
G171: H12.12 R99.2 U21.1(S12) X4.44
G172: H12.13 R101.2 U21.48(S13) X4.45
G173: H12.14 R103.2 U21.47(S14) X5.1
G174: H12.15 R105.2 U21.46(S15) X5.2
G175: H12.16 R107.2 U21.45(S16) X5.3
G176: H15.1 R109.2 U21.25(S17) X5.4
G177: H15.2 R111.2 U21.26(S18) X5.5
G178: H15.3 R113.2 U21.27(S19) X5.6
G179: H15.4 R115.2 U21.28(S20) X5.7
G180: H15.5 R117.2 U21.29(S21) X5.8
G181: H15.6 R119.2 U21.30(S22) X5.9
G182: H15.7 R121.2 U21.31(S23) X5.10
G183: H15.8 R123.2 U21.32(S24) X5.11
G184: H15.9 R125.2 U21.33(S25) X5.12
G185: H15.10 R127.2 U21.34(S26) X5.13
G186: H15.11 R129.2 U21.35(S27) X5.14
G187: H15.12 R131.2 U21.36(S28) X5.15
G188: H15.13 R133.2 U21.37(S29) X5.16
G189: H15.14 R135.2 U21.38(S30) X5.17
G190: H15.15 R137.2 U21.39(S31) X5.18
G191: H15.16 R140.2 U21.40(S32) X5.19
G192: H13.1 R142.2 U8.12(S1) X5.20
G193: H13.2 R144.2 U8.11(S2) X5.21
G194: H13.3 R146.2 U8.10(S3) X5.22
G195: H13.4 R148.2 U8.9(S4) X5.23
G196: H13.5 R150.2 U8.8(S5) X5.24
G197: H13.6 R152.2 U8.7(S6) X5.25
G198: H13.7 R154.2 U8.6(S7) X5.26
G199: H13.8 R156.2 U8.5(S8) X5.27
G200: H13.9 R158.2 U8.4(S9) X5.28
G201: H13.10 R160.2 U8.3(S10) X5.29
G202: H13.11 R162.2 U8.2(S11) X5.30
G203: H13.12 R164.2 U8.1(S12) X5.31
G204: H13.13 R166.2 U8.48(S13) X5.32
G205: H13.14 R168.2 U8.47(S14) X5.33
G206: H13.15 R170.2 U8.46(S15) X5.34
G207: H13.16 R172.2 U8.45(S16) X5.35
G208: H16.1 R174.2 U8.25(S17) X5.36
G209: H16.2 R176.2 U8.26(S18) X5.37
G210: H16.3 R178.2 U8.27(S19) X5.38
G211: H16.4 R180.2 U8.28(S20) X5.39
G212: H16.5 R182.2 U8.29(S21) X5.40
G213: H16.6 R184.2 U8.30(S22) X5.41
G214: H16.7 R186.2 U8.31(S23) X5.42
G215: H16.8 R188.2 U8.32(S24) X5.43
G216: H16.9 R190.2 U8.33(S25) X5.44
G217: H16.10 R192.2 U8.34(S26) X5.45
G218: H16.11 R194.2 U8.35(S27) X6.1
G219: H16.12 R196.2 U8.36(S28) X6.2
G220: H16.13 R198.2 U8.37(S29) X6.3
G221: H16.14 R200.2 U8.38(S30) X6.4
G222: H16.15 R202.2 U8.39(S31) X6.5
G223: H16.16 R204.2 U8.40(S32) X6.6
G224: H10.1 R206.2 U9.12(S1) X6.7
G225: H10.2 R208.2 U9.11(S2) X6.8
G226: H10.3 R210.2 U9.10(S3) X6.9
G227: H10.4 R212.2 U9.9(S4) X6.10
G228: H10.5 R214.2 U9.8(S5) X6.11
G229: H10.6 R216.2 U9.7(S6) X6.12
G230: H10.7 R218.2 U9.6(S7) X6.13
G231: H10.8 R220.2 U9.5(S8) X6.14
G232: H10.9 R222.2 U9.4(S9) X6.15
G233: H10.10 R224.2 U9.3(S10) X6.16
G234: H10.11 R226.2 U9.2(S11) X6.17
G235: H10.12 R228.2 U9.1(S12) X6.18
G236: H10.13 R230.2 U9.48(S13) X6.19
G237: H10.14 R232.2 U9.47(S14) X6.20
G238: H10.15 R234.2 U9.46(S15) X6.21
G239: H10.16 R236.2 U9.45(S16) X6.22
G240: H17.1 R238.2 U9.25(S17) X6.23
G241: H17.2 R240.2 U9.26(S18) X6.24
G242: H17.3 R242.2 U9.27(S19) X6.25
G243: H17.4 R244.2 U9.28(S20) X6.26
G244: H17.5 R246.2 U9.29(S21) X6.27
G245: H17.6 R248.2 U9.30(S22) X6.28
G246: H17.7 R250.2 U9.31(S23) X6.29
G247: H17.8 R252.2 U9.32(S24) X6.30
G248: H17.9 R254.2 U9.33(S25) X6.31
G249: H17.10 R256.2 U9.34(S26) X6.32
G250: H17.11 R258.2 U9.35(S27) X6.33
G251: H17.12 R260.2 U9.36(S28) X6.34
G252: H17.13 R262.2 U9.37(S29) X6.35
G253: H17.14 R264.2 U9.38(S30) X6.36
G254: H17.15 R266.2 U9.39(S31) X6.37
G255: H17.16 R268.2 U9.40(S32) X6.38
Gate: U10.2(VOUT) U13.3(IN+)
Gate1: U13.5(OUT) U22.3(Z)
Gate2-1: U6.43(D) U22.13(Y0)
Gate2-2: U7.43(D) U22.14(Y1)
Gate2-3: U11.43(D) U22.15(Y2)
Gate2-4: U12.43(D) U22.12(Y3)
Gate2-5: U20.43(D) U22.1(Y4)
Gate2-6: U21.43(D) U22.5(Y5)
Gate2-7: U8.43(D) U22.2(Y6)
Gate2-8: U9.43(D) U22.4(Y7)
SCL: M1.J4_78(78) U10.6(SCLK/SCL)
SDA: M1.J4_74(74) U10.8(SDIN/SDA)
SYNC: M1.J4_76(76) R138.1 U10.7(SYNC#/AO)
UART1_RXD: M1.J2_62(62)
UART1_TXD: M1.J2_59(59)
WR: M1.J4_52(52) U6.21(WR#) U7.21(WR#) U8.21(WR#) U9.21(WR#) U11.21(WR#) U12.21(WR#) U20.21(WR#) U21.21(WR#)
NetC17_2: C17.2 U10.10(VREFIO)

Not connected (* = marked no-connect by the designer): M1 J1_1(1) J1_2(2) J1_3(3) J1_4(4) J1_5(5) J1_6(6) J1_7(7) J1_8(8) J1_9(9) J1_10(10) J1_11(11) J1_12(12) J1_13(13) J1_14(14) J1_15(15) J1_16(16) J1_17(17) J1_18(18) J1_19(19) J1_20(20) J1_21(21) J1_22(22) J1_23(23) J1_24(24) J1_25(25) J1_26(26) J1_27(27) J1_28(28) J1_29(29) J1_30(30) J1_31(31) J1_32(32) J1_33(33) J1_34(34) J1_35(35) J1_36(36) J1_37(37) J1_38(38) J1_39(39) J1_40(40) J1_41(41) J1_42(42) J1_43(43) J1_44(44) J1_45(45) J1_46(46) J1_47(47) J1_48(48) J1_49(49) J1_50(50) J1_53(53) J1_54(54) J1_55(55) J1_56(56) J1_57(57) J1_58(58) J1_59(59) J1_60(60) J2_9(9) J2_10(10) J2_21(21) J2_22(22) J2_23(23) J2_24(24) J2_27(27) J2_29(29) J2_30(30) J2_31(31) J2_32(32) J2_33(33) J2_34(34) J2_35(35) J2_36(36) J2_37(37) J2_38(38) J2_39(39) J2_40(40) J2_41(41) J2_42(42) J2_43(43) J2_44(44) J2_45(45) J2_47(47) J2_48(48) J2_49(49) J2_50(50) J2_51(51) J2_52(52) J2_53(53) J2_54(54) J2_55(55) J2_56(56) J2_57(57) J2_58(58) J2_60(60) J2_61(61) J2_65(65) J2_66(66) J2_67(67) J2_68(68) J2_69(69) J2_70(70) J2_71(71) J2_72(72) J2_73(73) J2_74(74) J2_75(75) J2_76(76) J2_77(77) J2_78(78) J2_79(79) J2_80(80) J3_1(1) J3_2(2) J3_3(3) J3_4(4) J3_7(7) J3_8(8) J3_9(9) J3_10(10) J3_13(13) J3_14(14) J3_15(15) J3_16(16) J3_19(19) J3_20(20) J3_21(21) J3_22(22) J3_25(25) J3_26(26) J3_27(27) J3_28(28) J3_34(34) J3_36(36) J3_40(40) J3_41(41) J3_42(42) J3_43(43) J3_44(44) J3_45(45) J3_46(46) J3_47(47) J3_49(49) J3_50(50) J3_51(51) J3_52(52) J3_53(53) J3_54(54) J3_55(55) J3_56(56) J3_57(57) J3_58(58) J3_59(59) J3_60(60) J4_7(7) J4_8(8) J4_9(9) J4_10(10) J4_11(11) J4_12(12) J4_13(13) J4_14(14) J4_15(15) J4_16(16) J4_17(17) J4_18(18) J4_19(19) J4_20(20) J4_21(21) J4_22(22) J4_23(23) J4_24(24) J4_25(25) J4_26(26) J4_27(27) J4_28(28) J4_29(29) J4_30(30) J4_31(31) J4_32(32) J4_33(33) J4_34(34) J4_35(35) J4_36(36) J4_37(37) J4_38(38) J4_39(39) J4_40(40) J4_41(41) J4_42(42) J4_43(43) J4_44(44) J4_45(45) J4_47(47) J4_49(49) J4_50(50) J4_51(51) J4_53(53) J4_55(55) J4_57(57) J4_75(75) J4_77(77) J4_79(79); U6 41(NIC) 42(NIC) 44(NIC); U7 41(NIC) 42(NIC) 44(NIC); U8 41(NIC) 42(NIC) 44(NIC); U9 41(NIC) 42(NIC) 44(NIC); U10 3(NC) 9(NC); U11 41(NIC) 42(NIC) 44(NIC); U12 41(NIC) 42(NIC) 44(NIC); U20 41(NIC) 42(NIC) 44(NIC); U21 41(NIC) 42(NIC) 44(NIC); X3 39 40 41 42 43 44 45; X6 39 40 41 42 43 44 45

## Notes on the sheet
- FPC连接器
- 连接器

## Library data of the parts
C17 C20-C27 C29-C31 = C
E1 = CT: 贴片钽电容; 淘宝ID: 封装库来自淘宝 ID：黄晶宝石
H2-H17 = BX-PZ1.27-1-16PZZ: Manufacturer: Bossie(博锡); Add into BOM: yes; Pin Structure: 1x16P; Pitch: 1.27mm; Circluar Pins/Square Pins: 方针; Current Rating: 1A
M1 = Artix7 Core connector: 达芬奇pro A7核心板连接器
R13-R137 R139-R269 = 0402WGF1002TCE: Manufacturer: UNI-ROYAL(厚声); Add into BOM: yes; Tolerance: ±1%; Power(Watts): 62.5mW; Voltage-Supply(Max): 50V; Temperature Coefficient: ±100ppm/℃
R138 = R: 贴片电阻; 版权归属: 来自淘宝 ID：黄晶宝石; 封装库来自淘宝卖家 ID：黄晶宝石: 其他店铺购入均为盗版，不享受售后技术支持服务，请立即申请退款
U6-U9 U11 U12 U20 U21 = ADG732BSUZ-REEL: Manufacturer: ADI(亚德诺); Add into BOM: yes; Number of Channels: 32; Voltage - Supply: 1.8V~5.5V; RDS(on): 7Ω
U10 = DAC80501ZDGSR: Manufacturer: TI(德州仪器); Add into BOM: yes; Resolution(Bits): 16位; Number of Channels: 1; Interface: SPI；I2C; Voltage - Supply: 2.7V~5.5V; Settling Time: 5us; Integral non - linearity: 1LSB; Power-On Reset: 内置; Voltage Reference Drift: 5ppm/℃; Data rate: 1MHz；50MHz; Supply Current (Iq): 15uA
U13 = UCC27517DBVR: Manufacturer: TI(德州仪器); Add into BOM: yes; Driven Configuration: 低边; Load Type: IGBT；MOSFET; Number of Drivers: 1; Current - Output Low(IOL): 4A; Voltage - Supply: 4.5V~18V; Rise Time: 8ns; Fall Time: 7ns; Input Logic Level - High: 2.2V~2.4V; Input Logic Level - Low: 1V~1.2V
U22 = 74HC4051PW,118: Manufacturer: Nexperia(安世); Add into BOM: yes; Switch Circuit: 单刀八掷(SP8T); Number of Channels: 8; Voltage - Supply: 2V~10V; Turn-on time: 345ns; RDS(on): 225Ω; Turn-off time: 365ns
X1-X6 = AFC01-S45FCA-00: Manufacturer: JS(钜硕电子); Add into BOM: yes; Locking Feature: 翻盖式; Number of Contacts: 45P; Pitch: 0.5mm; FFC, FCB Thickness: 0.3mm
